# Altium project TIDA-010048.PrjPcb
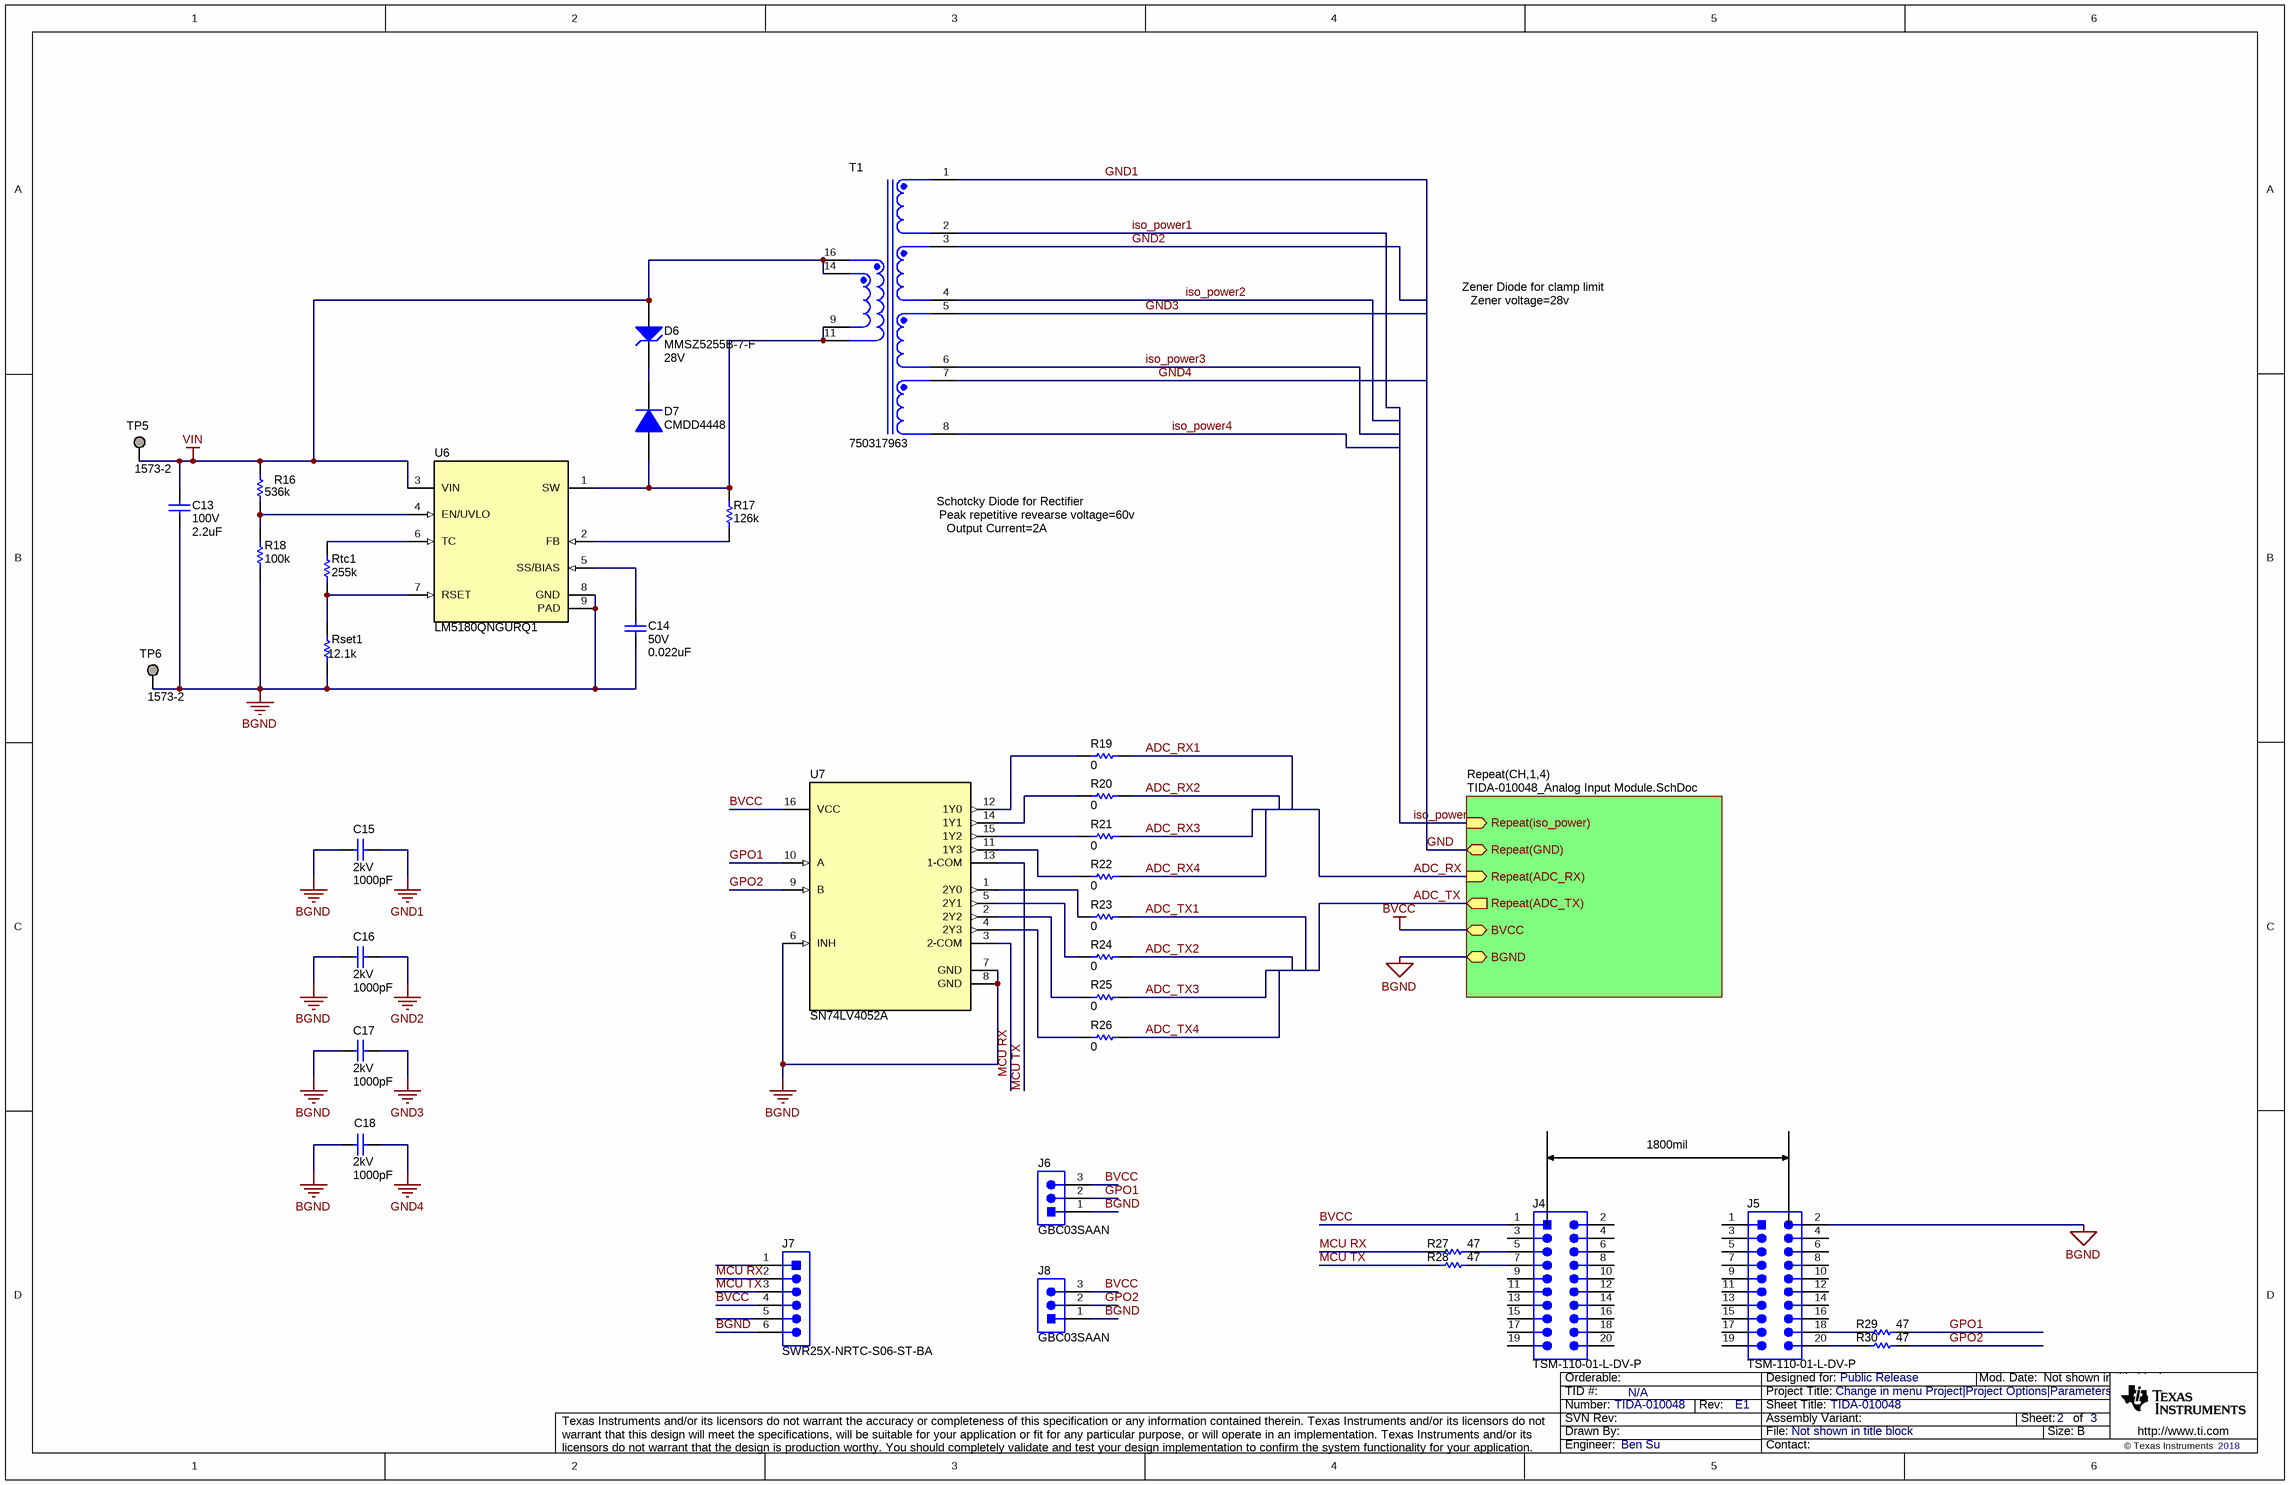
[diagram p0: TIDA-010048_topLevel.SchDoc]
Contact: http://www.ti.com/support; CopyrightYear: 2018; PCB_Layout: Who did the Layout?; PCB_Rev: E1; PRJ_Customer: Public Release; PRJ_Engineer: Ben Su; PRJ_Number: TIDA-010048; PRJ_Title: Change in menu Project|Project Options|Parameters; SCH_Rev: E1; TID: N/A
4 sheets, 256 parts. Net scope: hierarchical (ports join the sheet entries above them; power ports are global).
Board file: TIDA-010048_PCB.PcbDoc
Sheets:
  TIDA-010048_topLevel.SchDoc
    CH1 = TIDA-010048_Analog Input Module.SchDoc
    CH2 = TIDA-010048_Analog Input Module.SchDoc
    CH3 = TIDA-010048_Analog Input Module.SchDoc
    CH4 = TIDA-010048_Analog Input Module.SchDoc
  TIDA-010048_CoverSheet.SchDoc
  TIDA-010048_EVM_Hardware.SchDoc

## Sheet TIDA-010048_topLevel.SchDoc: TIDA-010048
size 431 x 279 mm; Date: Not shown in title block; ApprovedBy: Not shown in title block; CheckedBy: Not shown in title block; Author: Not shown in title block; CompanyName: Not shown in title block; Engineer: Not shown in title block; Organization: Not shown in title block; Address1: Not shown in title block; Address2: Not shown in title block; Address3: Not shown in title block; Address4: Not shown in title block; DocumentNumber: 1; Revision: Use project parameter SCH_Rev; SheetNumber: 2; SheetTotal: 3; PageSetup: Record=PageOptions¦CenterHorizontal=True¦CenterVertical=True¦PrintScale=1.00¦XCorrection=1.00¦YCorrection=1.00¦PrintKind=0¦BorderSize=5000000¦LeftOffset=0¦BottomOffset=0¦Orientation=2¦PaperLength=1000¦PaperWidth=1000¦Scale=100¦PaperSource=15¦PrintQuality=600¦MediaType=1¦DitherType=10¦PaperKind=Letter¦PrintScaleMode=1

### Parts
C13  VDC_V: 100V  ValueDisplayed: 2.2uF  [1210_210]  (hidden comment: C1210C225K1RACTU)
C14  VDC_V: 50V  ValueDisplayed: 0.022uF  [0603]  (hidden comment: C0603X223K5RACTU)
C15  VDC_V: 2kV  ValueDisplayed: 1000pF  [1812]  (hidden comment: GR443QR73D102KW01L)
C16  VDC_V: 2kV  ValueDisplayed: 1000pF  [1812]  (hidden comment: GR443QR73D102KW01L)
C17  VDC_V: 2kV  ValueDisplayed: 1000pF  [1812]  (hidden comment: GR443QR73D102KW01L)
C18  VDC_V: 2kV  ValueDisplayed: 1000pF  [1812]  (hidden comment: GR443QR73D102KW01L)
D6  MMSZ5255B-7-F  value 28V  [SOD-123]
D7  CMDD4448  [SOD-323]
J4  TSM-110-01-L-DV-P  [CONN_TSM-110-01-T-DV-P]
J5  TSM-110-01-L-DV-P  [CONN_TSM-110-01-T-DV-P]
J6  GBC03SAAN  [Sullins_Gxx03SAAN]
J7  SWR25X-NRTC-S06-ST-BA  [Sullins_SWR25X-NRTC-S06-ST-BA]
J8  GBC03SAAN  [Sullins_Gxx03SAAN]
R16  ValueDisplayed: 536k  [0603]  (hidden comment: RC0603FR-07536KL)
R17  ValueDisplayed: 126k  [0603]  (hidden comment: RT0603DRE07126KL)
R18  ValueDisplayed: 100k  [0603]  (hidden comment: RC0603FR-07100KL)
R19  ValueDisplayed: 0  [0603]  (hidden comment: CRCW06030000Z0EA)
R20  ValueDisplayed: 0  [0603]  (hidden comment: CRCW06030000Z0EA)
R21  ValueDisplayed: 0  [0603]  (hidden comment: CRCW06030000Z0EA)
R22  ValueDisplayed: 0  [0603]  (hidden comment: CRCW06030000Z0EA)
R23  ValueDisplayed: 0  [0603]  (hidden comment: CRCW06030000Z0EA)
R24  ValueDisplayed: 0  [0603]  (hidden comment: CRCW06030000Z0EA)
R25  ValueDisplayed: 0  [0603]  (hidden comment: CRCW06030000Z0EA)
R26  ValueDisplayed: 0  [0603]  (hidden comment: CRCW06030000Z0EA)
R27  ValueDisplayed: 47  [0603]  (hidden comment: CRCW060347R0JNEA)
R28  ValueDisplayed: 47  [0603]  (hidden comment: CRCW060347R0JNEA)
R29  ValueDisplayed: 47  [0603]  (hidden comment: CRCW060347R0JNEA)
R30  ValueDisplayed: 47  [0603]  (hidden comment: CRCW060347R0JNEA)
Rset1  ValueDisplayed: 12.1k  [0603]  (hidden comment: RC0603FR-0712K1L)
Rtc1  ValueDisplayed: 255k  [0603]  (hidden comment: RC0603FR-07255KL)
T1  750317963  [Wurth_750317963]
TP5  1573-2  [Keystone1573-2]
TP6  1573-2  [Keystone1573-2]
U6  LM5180QNGURQ1  [NGU0008C]
U7  SN74LV4052A  [PW0016A_L]

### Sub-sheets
Repeat(CH,1,4) = TIDA-010048_Analog Input Module.SchDoc: Repeat(iso_power) (in), Repeat(ADC_TX) (out), Repeat(ADC_RX) (in), BVCC (bidir), Repeat(GND), BGND (bidir)

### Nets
BGND: C13.2 C14.2 C15.2 C16.2 C17.2 C18.2 J5.2 J6.1 J7.6 J8.1 R18.1 Rset1.1 TP6.1 U6.8(GND) U6.9(PAD) U7.6(INH) U7.7(GND) U7.8(GND) ; sheet Repeat(CH,1,4)/BGND
BVCC: J4.1 J6.3 J7.4 J8.3 U7.16(VCC) ; sheet Repeat(CH,1,4)/BVCC
GND1: C15.1 C16.1 C17.1 C18.1 T1.1 T1.3 T1.5 T1.7  [also labelled GND2, GND3, GND4]  [project net GND]
VIN: C13.1 D6.2(A) R16.2 T1.14 T1.16 TP5.1 U6.3(VIN)
ADC_RX1: R19.2
ADC_RX2: R20.2
ADC_RX3: R21.2
ADC_RX4: R22.2
ADC_TX1: R23.2
ADC_TX2: R24.2
ADC_TX3: R25.2
ADC_TX4: R26.2
GPO1: J6.2 R29.2 U7.10(A)
GPO2: J8.2 R30.2 U7.9(B)
iso_power1: T1.2
iso_power2: T1.4
iso_power3: T1.6
iso_power4: T1.8
MCU RX: J7.2 R27.1 U7.3(2-COM)
MCU TX: J7.3 R28.1 U7.13(1-COM)
NetC14_1: C14.1 U6.5(SS/BIAS)
NetD6_1: D6.1(K) D7.1(K)
NetD7_2: D7.2(A) R17.2 T1.9 T1.11 U6.1(SW)
NetJ4_5: J4.5 R27.2
NetJ4_7: J4.7 R28.2
NetJ5_18: J5.18 R29.1
NetJ5_20: J5.20 R30.1
NetR16_1: R16.1 R18.2 U6.4(EN/UVLO)
NetR17_1: R17.1 U6.2(FB)
NetR19_1: R19.1 U7.12(1Y0)
NetR20_1: R20.1 U7.14(1Y1)
NetR21_1: R21.1 U7.15(1Y2)
NetR22_1: R22.1 U7.11(1Y3)
NetR23_1: R23.1 U7.1(2Y0)
NetR24_1: R24.1 U7.5(2Y1)
NetR25_1: R25.1 U7.2(2Y2)
NetR26_1: R26.1 U7.4(2Y3)
NetRset1_2: Rset1.2 Rtc1.1 U6.7(RSET)
NetRtc1_2: Rtc1.2 U6.6(TC)

Not connected (* = marked no-connect by the designer): J4 2 3 4 6 8 9 10 11 12 13 14 15 16 17 18 19 20; J5 1 3 4 5 6 7 8 9 10 11 12 13 14 15 16 17 19; J7 1 5

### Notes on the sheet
- Zener voltage=28v
- Zener Diode for clamp limit
- Schotcky Diode for Rectifier
- Output Current=2A
- Peak repetitive revearse voltage=60v
- 1800mil

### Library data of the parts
C13 = CMP-0009084-1: CAP, CERM, 2.2 uF, 100 V, +/- 10%, X7R, 1210; Manufacturer: Kemet; TaMin_C: -55°C; Polarized: N; SizeAreaWB_mm2: 14.7; Value1: Unknown; U/M: EA; Value: 2.2uF; TaMax_C: 125°C; SizeZ_mm: 2.1; SizeX_mm: 3.2; SizeY_mm: 2.5; Cap_Case: 1210; SizeArea_mm2: 8; CompType: Capacitor; Cap_F: 2.2µF; AEC Category: Q200
C14 = CMP-0006984-4: CAP, CERM, 0.022 uF, 50 V, +/- 10%, X7R, 0603; Manufacturer: Kemet; TaMin_C: -55°C; Polarized: N; SizeAreaWB_mm2: 4.68; Value1: Unknown; U/M: EA; TaMax_C: 125°C; SizeZ_mm: 1; SizeX_mm: 1.6; SizeY_mm: 0.8; SizeArea_mm2: 1.28; CompType: Capacitor; Cap_F: 22nF; AEC Category: Q200
C15-C18 = CMP-0009438-2: CAP, CERM, 1000 pF, 2000 V, +/- 10%, X7R, 1812; Manufacturer: MuRata; TaMin_C: -55°C; Polarized: N; SizeAreaWB_mm2: 23.1; Value1: Unknown; U/M: EA; Value: 1000pF; TaMax_C: 125°C; SizeZ_mm: 1.35; SizeX_mm: 4.5; SizeY_mm: 3.2; Value2: 2000V; SizeArea_mm2: 14.4; Cap_F: 1nF; AEC Category: Q200
D6 = CMP-0005760-4: Diode, Zener, 28 V, 500 mW, SOD-123; Manufacturer: Diodes Inc.; SizeArea_mm2: 6.545; Value1: 0.5W; SizeZ_mm: 1.35; AEC Category: Q101; SizeY_mm: 1.7; Power_W: 500mW; SizeAreaWB_mm2: 13.095; RJA_CperW: 350; SizeX_mm: 3.85
D7 = CMP-0029019-2: Diode, Ultrafast, 75 V, 0.25 A, SOD-323; Manufacturer: Central Semiconductor; Io_A: 2.5dA; SizeX_mm: 2.7; Vf_V: 1.2V; TJmax_C: 175°C; SizeAreaWB_mm2: 8.695; SizeArea_mm2: 3.645; Vr_V: 75V; Green_Lifecycle: Not Set; Green_REACh: Incomplete; AEC Category: Q101; Value: 75V; Value1: 0.25A; SizeZ_mm: 1; SizeY_mm: 1.35
J4 J5 = CMP-0075600-1: Header, 2.54mm, 10x2, Gold, SMT; Manufacturer: Samtec; Pitch_mm: 2.54; Gender: Male; Cert_CSA: Y; Green_REACh: Passed; Current_A: 5.4A; Voltage_V: 475V; CT: False; Shrouded: N; Green_Lifecycle: Active; Row_Count: 2; CNHeader: True
J6 J8 = CMP-0054577-1: Header, 2.54 mm, 3x1, Gold, TH; Manufacturer: Sullins Connector Solutions; CT: FALSE; CNHeader: TRUE
J7 = CMP-0054740-1: Header, 2.54mm, 6x1, Tin, TH; Manufacturer: Sullins Connector Solutions; CNHeader: FALSE; Current_A: 3A; Gender: Male; Voltage_V: 250V; Row_Count: 1; Pitch_mm: 2.54; Cert_UL: Y
R16 = CMP-0023174-4: RES, 536 k, 1%, 0.1 W, 0603; Manufacturer: Yageo; Power_W: 100mW; TempCo: 100 ppm/C; Value: 536k; EIA_Code: E96; SizeX_mm: 1.6; SizeY_mm: 0.8; SizeZ_mm: 1; Value2: 0.1W; SizeArea_mm2: 1.28; CompType: Resistor; AEC Qualified: N; VDC_V: 75V; AEC Category: Q200; SizeAreaWB_mm2: 4.68
R17 = CMP-0024631-2: RES, 126 k, 0.5%, 0.1 W, 0603; Manufacturer: Yageo America; Power_W: 100mW; TempCo: 50 ppm/C; U/M: EA; Value: 126k; EIA_Code: E192; SizeX_mm: 1.6; SizeY_mm: 0.8; SizeZ_mm: 1; Value2: 0.1W; SizeArea_mm2: 1.28; CompType: Resistor; VDC_V: 75V; AEC Category: Q200
R18 = CMP-0022735-5: RES, 100 k, 1%, 0.1 W, 0603; Manufacturer: Yageo; Power_W: 100mW; TempCo: 100 ppm/C; Value: 100k; EIA_Code: E96; SizeX_mm: 1.6; SizeY_mm: 0.8; SizeZ_mm: 1; Value2: 0.1W; SizeArea_mm2: 1.28; CompType: Resistor; AEC Qualified: N; VDC_V: 75V; AEC Category: Q200; SizeAreaWB_mm2: 4.68
R19-R26 = CMP-0025697-4: RES, 0, 5%, 0.1 W, AEC-Q200 Grade 0, 0603; Manufacturer: Vishay-Dale; Power_W: 100mW; TempCo: 200 ppm/C; Value_Code: 0000; Value: 0; EIA_Code: E24; SizeX_mm: 1.6; SizeY_mm: 0.8; SizeZ_mm: 1; Value2: 0.1W; SizeArea_mm2: 1.28; AEC Qualified: Y; VDC_V: 75V; AEC Category: Q200
R27-R30 = CMP-0025815-2: RES, 47, 5%, 0.1 W, 0603; Manufacturer: Vishay-Dale; Power_W: 100mW; TempCo: 200 ppm/C; Value_Code: 47R0; U/M: EA; Value: 47; EIA_Code: E24; SizeX_mm: 1.6; SizeY_mm: 0.8; SizeZ_mm: 1; Value2: 0.1W; SizeArea_mm2: 1.28; VDC_V: 75V; AEC Category: Q200
Rset1 = CMP-0022776-5: RES, 12.1 k, 1%, 0.1 W, 0603; Manufacturer: Yageo; Power_W: 100mW; TempCo: 100 ppm/C; Value_Code: 12k1; Value: 12.1k; EIA_Code: E96; SizeX_mm: 1.6; SizeY_mm: 0.8; SizeZ_mm: 1; Value2: 0.1W; SizeArea_mm2: 1.28; CompType: Resistor; AEC Qualified: N; VDC_V: 75V; AEC Category: Q200; SizeAreaWB_mm2: 4.68
Rtc1 = CMP-0022949-4: RES, 255 k, 1%, 0.1 W, 0603; Manufacturer: Yageo; Power_W: 100mW; TempCo: 100 ppm/C; Value: 255k; EIA_Code: E96; SizeX_mm: 1.6; SizeY_mm: 0.8; SizeZ_mm: 1; Value2: 0.1W; SizeArea_mm2: 1.28; CompType: Resistor; AEC Qualified: N; VDC_V: 75V; AEC Category: Q200; SizeAreaWB_mm2: 4.68
T1 = CMP-0084723-1: Transformer, 22 uH, TH; Manufacturer: Wurth Elektronik; Rsec2_ohm: 4.25d; DCR_ohm: 0.036; Value: 22uH; Ind_H: 22µH; LeakageInd_H: 75nH; SizeArea_mm2: 213.0425; SizeAreaWB_mm2: 275.4825; SizeY_mm: 15.25; Ns1toNp: 2; SizeX_mm: 13.97; Rsec3_ohm: 5.15d; AEC Qualified: N; AEC Category: Q200; Lp: 22; SizeZ_mm: 12.7
TP5 TP6 = CMP-0055119-1: Terminal, Turret, TH, Double; Manufacturer: Keystone; CT: FALSE; Green_REACh: Passed; CompType: Turret Terminal; Green_Lifecycle: Active
U6 = CMP-0078633-2: 70-V PSR Flyback Converter With 100-V, 1.2-A Power Switch and Ultra-Low IQ, NGU0008C (WSON-8); Alternate PartNumber: LM5180QNGUTQ1; Alternate Manufacturer: Texas Instruments; SizeAreaWB_mm2: 25; SizeZ_mm: 0.8; SizeX_mm: 4; SizeArea_mm2: 16; CompType: IC; AEC Qualified: Y; AEC Category: Q200
U7 = CMP-0066257-1: Automotive Catalog Dual 4-Channel Analog Multiplexer/Demultiplexer, PW0016A (TSSOP-16); Alternate Manufacturer: Texas Instruments; SizeAreaWB_mm2: 58.8; U/M: EA; SizeZ_mm: 1.2; SizeX_mm: 6.4; SizeY_mm: 5.0; SizeArea_mm2: 32.0; CompType: IC

## Sheet TIDA-010048_Analog Input Module.SchDoc
size 431 x 279 mm; Date: Not shown in title block; ApprovedBy: Not shown in title block; CheckedBy: Not shown in title block; Author: Not shown in title block; CompanyName: Not shown in title block; Engineer: Not shown in title block; Organization: Not shown in title block; Address1: Not shown in title block; Address2: Not shown in title block; Address3: Not shown in title block; Address4: Not shown in title block; DocumentNumber: 1; Revision: Use project parameter SCH_Rev; SheetNumber: 2; SheetTotal: 3; PageSetup: Record=PageOptions¦CenterHorizontal=True¦CenterVertical=True¦PrintScale=1.00¦XCorrection=1.00¦YCorrection=1.00¦PrintKind=0¦BorderSize=5000000¦LeftOffset=0¦BottomOffset=0¦Orientation=2¦PaperLength=1000¦PaperWidth=1000¦Scale=100¦PaperSource=15¦PrintQuality=600¦MediaType=1¦DitherType=10¦PaperKind=Letter¦PrintScaleMode=1
Used 4 times, as channels CH1, CH2, CH3, CH4. Parts and nets are listed once, with the designators drawn on the sheet.
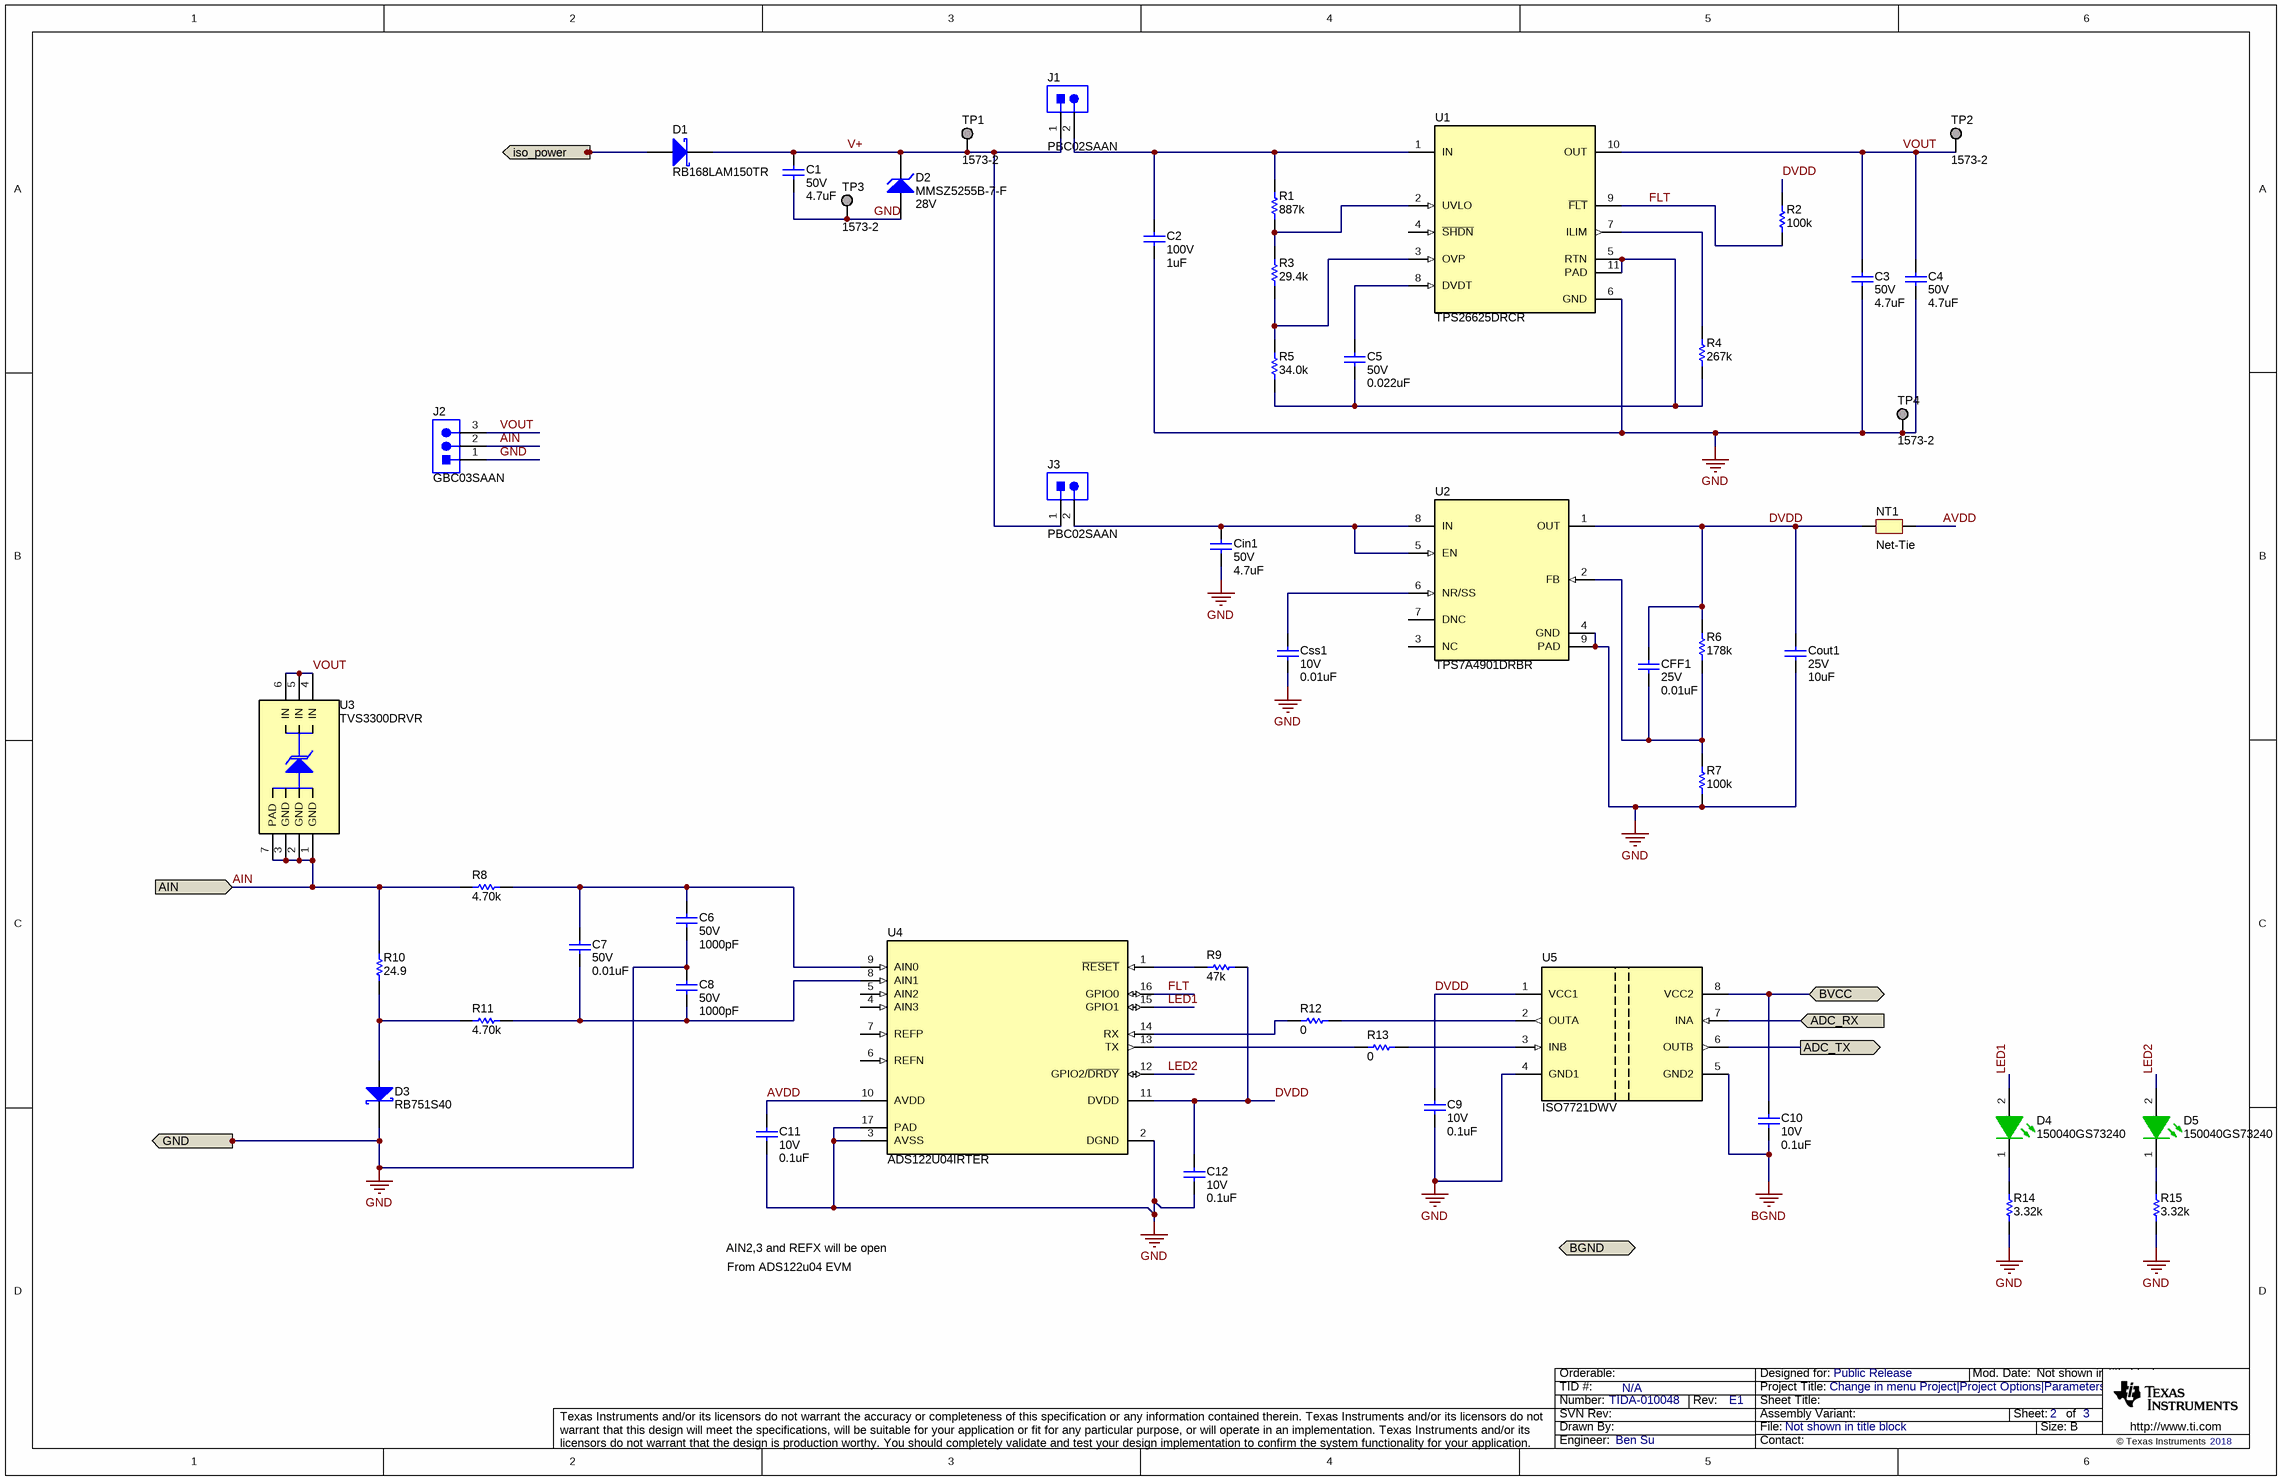
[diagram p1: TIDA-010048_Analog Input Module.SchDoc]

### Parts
C1  VDC_V: 50V  ValueDisplayed: 4.7uF  [0805_HV]  (hidden comment: C2012X5R1H475K125AB)
C2  VDC_V: 100V  ValueDisplayed: 1uF  [1206_180]  (hidden comment: C3216X7R2A105K160AA)
C3  VDC_V: 50V  ValueDisplayed: 4.7uF  [0805_HV]  (hidden comment: C2012X5R1H475K125AB)
C4  VDC_V: 50V  ValueDisplayed: 4.7uF  [0805_HV]  (hidden comment: C2012X5R1H475K125AB)
C5  VDC_V: 50V  ValueDisplayed: 0.022uF  [0603]  (hidden comment: C0603X223K5RACTU)
C6  VDC_V: 50V  ValueDisplayed: 1000pF  [0603]  (hidden comment: C0603C102J5GACTU)
C7  VDC_V: 50V  ValueDisplayed: 0.01uF  [0603]  (hidden comment: GRM1885C1H103JA01D)
C8  VDC_V: 50V  ValueDisplayed: 1000pF  [0603]  (hidden comment: C0603C102J5GACTU)
C9  VDC_V: 10V  ValueDisplayed: 0.1uF  [0603]  (hidden comment: C0603C104K8RACTU)
C10  VDC_V: 10V  ValueDisplayed: 0.1uF  [0603]  (hidden comment: C0603C104K8RACTU)
C11  VDC_V: 10V  ValueDisplayed: 0.1uF  [0603]  (hidden comment: C0603C104K8RACTU)
C12  VDC_V: 10V  ValueDisplayed: 0.1uF  [0603]  (hidden comment: C0603C104K8RACTU)
CFF1  VDC_V: 25V  ValueDisplayed: 0.01uF  [0603]  (hidden comment: GRM188R71E103KA01D)
Cin1  VDC_V: 50V  ValueDisplayed: 4.7uF  [0805_HV]  (hidden comment: C2012X5R1H475K125AB)
Cout1  VDC_V: 25V  ValueDisplayed: 10uF  [1210_280]  (hidden comment: C3225X7R1E106M250AC)
Css1  VDC_V: 10V  ValueDisplayed: 0.01uF  [0603]  (hidden comment: 0603ZC103KAT2A)
D1  RB168LAM150TR  [SOD-128]
D2  MMSZ5255B-7-F  value 28V  [SOD-123]
D3  RB751S40  [Fairchild_SOD-523F]
D4  150040GS73240  [WL-SMCC_0402_Green]
D5  150040GS73240  [WL-SMCC_0402_Green]
J1  PBC02SAAN  [Sullins_PBC02SAAN]
J2  GBC03SAAN  [Sullins_Gxx03SAAN]
J3  PBC02SAAN  [Sullins_PBC02SAAN]
NT1  Net-Tie  [Net-Tie_0805_HV_NoOverlay]  (net tie, no BOM)
R1  ValueDisplayed: 887k  [0603]  (hidden comment: RC0603FR-07887KL)
R2  ValueDisplayed: 100k  [0603]  (hidden comment: RC0603FR-07100KL)
R3  ValueDisplayed: 29.4k  [0603]  (hidden comment: RC0603FR-0729K4L)
R4  ValueDisplayed: 267k  [0603]  (hidden comment: RC0603FR-07267KL)
R5  ValueDisplayed: 34.0k  [0603]  (hidden comment: RC0603FR-0734KL)
R6  ValueDisplayed: 178k  [0603]  (hidden comment: CRCW0603178KFKEA)
R7  ValueDisplayed: 100k  [0603]  (hidden comment: RC0603FR-07100KL)
R8  ValueDisplayed: 4.70k  [0805_HV]  (hidden comment: ERJ-P06F4701V)
R9  ValueDisplayed: 47k  [0603]  (hidden comment: CRCW060347K0JNEA)
R10  ValueDisplayed: 24.9  [0603]  (hidden comment: RNCF0603TKY24R9)
R11  ValueDisplayed: 4.70k  [0805_HV]  (hidden comment: ERJ-P06F4701V)
R12  ValueDisplayed: 0  [0603]  (hidden comment: CRCW06030000Z0EA)
R13  ValueDisplayed: 0  [0603]  (hidden comment: CRCW06030000Z0EA)
R14  ValueDisplayed: 3.32k  [0603]  (hidden comment: RC0603FR-073K32L)
R15  ValueDisplayed: 3.32k  [0603]  (hidden comment: RC0603FR-073K32L)
TP1  1573-2  [Keystone1573-2]
TP2  1573-2  [Keystone1573-2]
TP3  1573-2  [Keystone1573-2]
TP4  1573-2  [Keystone1573-2]
U1  TPS26625DRCR  [DRC0010J]
U2  TPS7A4901DRBR  [DRB0008A]
U3  TVS3300DRVR  [DRV0006A]
U4  ADS122U04IRTER  [RTE0016D]
U5  ISO7721DWV  [DWV0008A]

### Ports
ADC_RX (in), ADC_TX (out), AIN (in), BGND (bidir), BVCC (bidir), GND, iso_power (in)

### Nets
BGND: C10.2 U5.5(GND2)
GND: C1.2 C2.2 C3.2 C4.2 C6.2 C8.1 C9.2 C11.2 C12.2 Cin1.2 Cout1.2 Css1.2 D2.2(A) D3.1(K) J2.1 R7.1 R14.1 R15.1 TP3.1 TP4.1 U1.6(GND) U2.4(GND) U2.9(PAD) U4.2(DGND) U4.3(AVSS) U4.17(PAD) U5.4(GND1) ; port GND
ADC_RX: U5.7(INA) ; port ADC_RX
ADC_TX: U5.6(OUTB) ; port ADC_TX
AIN: J2.2 R8.1 R10.2 U3.1(GND) U3.2(GND) U3.3(GND) U3.7(PAD) ; port AIN
AVDD: C11.1 NT1.2 U4.10(AVDD)
BVCC: C10.1 U5.8(VCC2) ; port BVCC
DVDD: C9.1 C12.1 CFF1.1 Cout1.1 NT1.1 R2.2 R6.2 R9.2 U2.1(OUT) U4.11(DVDD) U5.1(VCC1)
FLT: R2.1 U1.9(~{FLT}) U4.16(GPIO0)
iso_power: D1.2(A) ; port iso_power
LED1: D4.2(A) U4.15(GPIO1)
LED2: D5.2(A) U4.12(GPIO2/~{DRDY})
V+: C1.1 D1.1(K) D2.1(K) J1.1 J3.1 TP1.1
VOUT: C3.1 C4.1 J2.3 TP2.1 U1.10(OUT) U3.4(IN) U3.5(IN) U3.6(IN)
NetC2_1: C2.1 J1.2 R1.2 U1.1(IN)
NetC5_1: C5.1 U1.8(DVDT)
NetC5_2: C5.2 R4.1 R5.1 U1.5(RTN) U1.11(PAD)
NetC6_1: C6.1 C7.1 R8.2 U4.9(AIN0)
NetC7_2: C7.2 C8.2 R11.2 U4.8(AIN1)
NetCFF1_2: CFF1.2 R6.1 R7.2 U2.2(FB)
NetCin1_1: Cin1.1 J3.2 U2.5(EN) U2.8(IN)
NetCss1_1: Css1.1 U2.6(NR/SS)
NetD3_2: D3.2(A) R10.1 R11.1
NetD4_1: D4.1(K) R14.2
NetD5_1: D5.1(K) R15.2
NetR1_1: R1.1 R3.2 U1.2(UVLO)
NetR3_1: R3.1 R5.2 U1.3(OVP)
NetR4_2: R4.2 U1.7(ILIM)
NetR9_1: R9.1 U4.1(~{RESET})
NetR12_1: R12.1 U4.14(RX)
NetR12_2: R12.2 U5.2(OUTA)
NetR13_1: R13.1 U4.13(TX)
NetR13_2: R13.2 U5.3(INB)

Not connected (* = marked no-connect by the designer): U1 4(~{SHDN}); U2 3(NC) 7(DNC); U4 4(AIN3) 5(AIN2) 6(REFN) 7(REFP)

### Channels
CH1: designators end in _CH1; ports ADC_RX=ADC_RX1 ADC_TX=ADC_TX1 AIN=AIN_CH1 BGND=BGND BVCC=BVCC GND=GND iso_power=iso_power1
CH2: designators end in _CH2; ports ADC_RX=ADC_RX2 ADC_TX=ADC_TX2 AIN=AIN_CH2 BGND=BGND BVCC=BVCC GND=GND iso_power=iso_power2
CH3: designators end in _CH3; ports ADC_RX=ADC_RX3 ADC_TX=ADC_TX3 AIN=AIN_CH3 BGND=BGND BVCC=BVCC GND=GND iso_power=iso_power3
CH4: designators end in _CH4; ports ADC_RX=ADC_RX4 ADC_TX=ADC_TX4 AIN=AIN_CH4 BGND=BGND BVCC=BVCC GND=GND iso_power=iso_power4

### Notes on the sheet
- From ADS122u04 EVM
- AIN2,3 and REFX will be open

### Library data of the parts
C1 C3 C4 Cin1 = CMP-0007840-2: CAP, CERM, 4.7 uF, 50 V, +/- 10%, X5R, 0805; Manufacturer: TDK; TaMin_C: -55°C; ESR_ohm: 2.346m; Polarized: N; SizeAreaWB_mm2: 6.75; Value1: 0.002346 ohm; U/M: EA; Value: 4.7uF; TaMax_C: 85°C; SizeZ_mm: 1.45; SizeX_mm: 2; SizeY_mm: 1.25; Cap_Case: 0805; SizeArea_mm2: 2.5; CompType: Capacitor; Cap_F: 4.7µF; IRMS_A: 4.26021A; AEC Category: Q200
C2 = CMP-0008710-2: CAP, CERM, 1 uF, 100 V, +/- 10%, X7R, 1206; Manufacturer: TDK; TaMin_C: -55°C; ESR_ohm: 4.575m; Polarized: N; SizeAreaWB_mm2: 10.92; Value1: 0.004575 ohm; U/M: EA; Value: 1uF; TaMax_C: 125°C; SizeZ_mm: 1.8; SizeX_mm: 3.2; SizeY_mm: 1.6; SizeArea_mm2: 5.12; CompType: Capacitor; Cap_F: 1µF; IRMS_A: 3.39639A; AEC Category: Q200
C5 = CMP-0006984-4: as C14 on sheet TIDA-010048_topLevel
C6 C8 = CMP-0006843-4: CAP, CERM, 1000 pF, 50 V, +/- 5%, C0G/NP0, 0603; Manufacturer: Kemet; TaMin_C: -55°C; Polarized: N; SizeAreaWB_mm2: 4.68; Value1: Unknown; U/M: EA; Value: 1000pF; TaMax_C: 125°C; SizeZ_mm: 1; SizeX_mm: 1.6; SizeY_mm: 0.8; SizeArea_mm2: 1.28; CompType: Capacitor; Cap_F: 1nF; AEC Category: Q200
C7 = CMP-0007174-4: CAP, CERM, 0.01 uF, 50 V, +/- 5%, C0G/NP0, 0603; Manufacturer: MuRata; TaMin_C: -55°C; Polarized: N; SizeAreaWB_mm2: 4.68; Value1: Unknown; U/M: EA; Value: 0.01uF; TaMax_C: 125°C; SizeZ_mm: 1; SizeX_mm: 1.6; SizeY_mm: 0.8; SizeArea_mm2: 1.28; CompType: Capacitor; Cap_F: 10nF; AEC Category: Q200
C9-C12 = CMP-0006862-5: CAP, CERM, 0.1 uF, 10 V, +/- 10%, X7R, 0603; Manufacturer: Kemet; TaMin_C: -55°C; Polarized: N; SizeAreaWB_mm2: 4.68; Value1: Unknown; U/M: EA; Value: 0.1uF; TaMax_C: 125°C; SizeZ_mm: 1; SizeX_mm: 1.6; SizeY_mm: 0.8; SizeArea_mm2: 1.28; CompType: Capacitor; Cap_F: 100nF; AEC Category: Q200
CFF1 = CMP-0007403-4: CAP, CERM, 0.01 uF, 25 V, +/- 10%, X7R, 0603; Manufacturer: MuRata; TaMin_C: -55°C; Polarized: N; SizeAreaWB_mm2: 4.68; Value1: Unknown; U/M: EA; Value: 0.01uF; TaMax_C: 125°C; SizeZ_mm: 1; SizeX_mm: 1.6; SizeY_mm: 0.8; SizeArea_mm2: 1.28; CompType: Capacitor; Cap_F: 10nF; AEC Category: Q200
Cout1 = CMP-0009117-1: CAP, CERM, 10 uF, 25 V, +/- 20%, X7R, 1210; Manufacturer: TDK; TaMin_C: -55°C; Polarized: N; SizeAreaWB_mm2: 14.7; Value1: Unknown; U/M: EA; Value: 10uF; TaMax_C: 125°C; SizeZ_mm: 2.8; SizeX_mm: 3.2; SizeY_mm: 2.5; Cap_Case: 1210; SizeArea_mm2: 8; CompType: Capacitor; Cap_F: 10µF; AEC Category: Q200
Css1 = CMP-0006814-5: CAP, CERM, 0.01 uF, 10 V, +/- 10%, X7R, 0603; Manufacturer: AVX; TaMin_C: -55°C; Polarized: N; SizeAreaWB_mm2: 4.68; Value1: Unknown; U/M: EA; Value: 0.01uF; TaMax_C: 125°C; SizeZ_mm: 1; SizeX_mm: 1.6; SizeY_mm: 0.8; SizeArea_mm2: 1.28; CompType: Capacitor; Cap_F: 10nF; AEC Category: Q200
D1 = CMP-0080711-2: Diode, Schottky, 150 V, 1 A, SOD-128; Manufacturer: Rohm; AEC Category: Q101; AEC Qualified: N; TJmax_C: 150°C; Io_A: 1A; Vr_V: 150V; Value: 150V; Vf_V: 8.4dV; SizeX_mm: 4.6; SizeAreaWB_mm2: 19.6; Value2: 0.84V; SizeY_mm: 2.5; SizeZ_mm: 1.1; SizeArea_mm2: 11.5
D2 = CMP-0005760-3: Diode, Zener, 28 V, 500 mW, SOD-123; Manufacturer: Diodes Inc.; SizeX_mm: 3.85; AEC Category: Q101; SizeAreaWB_mm2: 13.095; Value1: 0.5W; SizeZ_mm: 1.35; RJA_CperW: 350; Power_W: 500mW; SizeArea_mm2: 6.545; SizeY_mm: 1.7
D3 = CMP-0028860-2: Diode, Schottky, 40 V, 0.03 A, SOD-523F; Manufacturer: Fairchild Semiconductor; SizeX_mm: 1.6; SizeY_mm: 0.8; Value1: 0.03A; TJmax_C: 125°C; AEC Qualified: N; SizeArea_mm2: 1.28; Vf_V: 3.7dV; AEC Category: Q101; Value: 40V; Io_A: 30mA; SizeAreaWB_mm2: 4.68; Value2: 0.37V; SizeZ_mm: 0.7; Green_Lifecycle: Not Set; Green_REACh: Incomplete
D4 D5 = CMP-0081765-2: LED, Green, SMD; Manufacturer: Wurth Elektronik; Vr_V: 5V; Io_A: 20mA; Tjmax_C: 95°C; Ir_A: 10µA; Power_TotalModule: 99mW; Value2: 3.2V; SizeArea_mm2: 0.5; SizeX_mm: 1; Value1: 0.099W; Angle: 120; Type: InGaN; SizeAreaWB_mm2: 3
J1 J3 = CMP-0054566-1: Header, 100mil, 2x1, Gold, TH; Manufacturer: Sullins Connector Solutions; CNHeader: TRUE; Current_A: 3A; Green_Lifecycle: Active; Shrouded: N; Gender: Male; Green_REACh: Passed; Voltage_V: 1.8kV; Row_Count: 1; Pitch_mm: 2.54; CT: FALSE; Cert_UL: Y
J2 = CMP-0054577-1: as J6 on sheet TIDA-010048_topLevel
NT1 = CMP-0078142-2: Single point connection between nets.
R1 = CMP-0023302-4: RES, 887 k, 1%, 0.1 W, 0603; Manufacturer: Yageo; Power_W: 100mW; TempCo: 100 ppm/C; Value: 887k; EIA_Code: E96; SizeX_mm: 1.6; SizeY_mm: 0.8; SizeZ_mm: 1; Value2: 0.1W; SizeArea_mm2: 1.28; CompType: Resistor; AEC Qualified: N; VDC_V: 75V; AEC Category: Q200; SizeAreaWB_mm2: 4.68
R2 R7 = CMP-0022735-5: as R18 on sheet TIDA-010048_topLevel
R3 = CMP-0022979-5: RES, 29.4 k, 1%, 0.1 W, 0603; Manufacturer: Yageo; Power_W: 100mW; TempCo: 100 ppm/C; Value_Code: 29k4; Value: 29.4k; EIA_Code: E96; SizeX_mm: 1.6; SizeY_mm: 0.8; SizeZ_mm: 1; Value2: 0.1W; SizeArea_mm2: 1.28; CompType: Resistor; AEC Qualified: N; VDC_V: 75V; AEC Category: Q200; SizeAreaWB_mm2: 4.68
R4 = CMP-0022955-4: RES, 267 k, 1%, 0.1 W, 0603; Manufacturer: Yageo; Power_W: 100mW; TempCo: 100 ppm/C; Value: 267k; EIA_Code: E96; SizeX_mm: 1.6; SizeY_mm: 0.8; SizeZ_mm: 1; Value2: 0.1W; SizeArea_mm2: 1.28; CompType: Resistor; AEC Qualified: N; VDC_V: 75V; AEC Category: Q200; SizeAreaWB_mm2: 4.68
R5 = CMP-0023045-5: RES, 34.0 k, 1%, 0.1 W, 0603; Manufacturer: Yageo; Power_W: 100mW; TempCo: 100 ppm/C; Value_Code: 34k0; Value: 34.0k; EIA_Code: E96; Res_ohm: 34k; SizeX_mm: 1.6; SizeY_mm: 0.8; SizeZ_mm: 1; Value2: 0.1W; SizeArea_mm2: 1.28; CompType: Resistor; AEC Qualified: N; VDC_V: 75V; AEC Category: Q200; SizeAreaWB_mm2: 4.68
R6 = CMP-0022087-4: RES, 178 k, 1%, 0.1 W, AEC-Q200 Grade 0, 0603; Manufacturer: Vishay-Dale; Power_W: 100mW; TempCo: 100 ppm/C; Value: 178k; EIA_Code: E96; SizeX_mm: 1.6; SizeY_mm: 0.8; SizeZ_mm: 1; Value2: 0.1W; SizeArea_mm2: 1.28; CompType: Resistor; AEC Qualified: Y; VDC_V: 75V; AEC Category: Q200; AEC Grade: 0
R8 R11 = CMP-0021852-2: RES, 4.70 k, 1%, 0.5 W, AEC-Q200 Grade 0, 0805; Manufacturer: Panasonic; Power_W: 500mW; TempCo: 100 ppm/C; Value_Code: 4k70; U/M: EA; Value: 4.70k; Res_ohm: 4.7k; SizeX_mm: 2; SizeY_mm: 1.25; SizeZ_mm: 1.45; Value2: 0.5W; SizeArea_mm2: 2.5; AEC Qualified: Y; VDC_V: 400V; AEC Grade: 0; AEC Category: Q200
R9 = CMP-0025814-2: RES, 47 k, 5%, 0.1 W, 0603; Manufacturer: Vishay-Dale; Power_W: 100mW; TempCo: 200 ppm/C; Value_Code: 47k0; U/M: EA; Value: 47k; EIA_Code: E24; SizeX_mm: 1.6; SizeY_mm: 0.8; SizeZ_mm: 1; Value2: 0.1W; SizeArea_mm2: 1.28; VDC_V: 75V; AEC Category: Q200
R10 = CMP-0083850-1: RES, 24.9, 0.01%, 0.1 W, AEC-Q200 Grade 0, 0603; Manufacturer: Stackpole Electronics Inc; Power_W: 100mW; TempCo: 5 ppm/C; SizeAreaWB_mm2: 4.68; Value_Code: 24R9; Value: 24.9; SizeX_mm: 1.6; SizeY_mm: 0.8; SizeZ_mm: 1; Value2: 0.1W; SizeArea_mm2: 1.28; CompType: Resistor; AEC Qualified: Y; VDC_V: 75V; AEC Grade: 0; AEC Category: Q200
R12 R13 = CMP-0025697-4: as R19 on sheet TIDA-010048_topLevel
R14 R15 = CMP-0023080-5: RES, 3.32 k, 1%, 0.1 W, 0603; Manufacturer: Yageo; Power_W: 100mW; TempCo: 100 ppm/C; Value_Code: 3k32; Value: 3.32k; EIA_Code: E96; SizeX_mm: 1.6; SizeY_mm: 0.8; SizeZ_mm: 1; Value2: 0.1W; SizeArea_mm2: 1.28; CompType: Resistor; AEC Qualified: N; VDC_V: 75V; AEC Category: Q200; SizeAreaWB_mm2: 4.68
TP1-TP4 = CMP-0055119-1: as TP5 on sheet TIDA-010048_topLevel
U1 = CMP-0013395-6: 60-V, 800-mA Industrial eFuse with Integrated Reverse Polarity Protection, DRC0010J (VSON-10); Alternate PartNumber: TPS26625DRCT; Manufacturer: Texas Instruments; SizeZ_mm: 1; SizeX_mm: 3; SizeArea_mm2: 9; CompType: IC; SizeAreaWB_mm2: 16; AEC Category: Q200; AEC Qualified: N; Rating: Catalog
U2 = CMP-0073868-3: Vin 3V to 36V, 150mA, Ultra-Low-Noise, High-PSRR Low-Dropout (LDO) Linear Regulator, DRB0008A (VSON-8); Manufacturer: Texas Instruments; Alternate PartNumber: TPS7A4901DRBT; AEC Category: Q200; CompType: IC; SizeZ_mm: 1.0; Rating: Catalog; SizeAreaWB_mm2: 16.0; SizeX_mm: 3.0; SizeArea_mm2: 9.0; AEC Qualified: N
U3 = CMP-0013424-7: 33-V Precision Surge Protection Clamp, DRV0006A (WSON-6); Manufacturer: Texas Instruments; Alternate PartNumber: TVS3300DRVT; SizeX_mm: 2; CompType: IC; SizeZ_mm: 0.8; SizeArea_mm2: 4; SizeAreaWB_mm2: 9; U/M: EA
U4 = CMP-0074857-3: 24-Bit, 2kSPS, 4-Ch, Low-Power Delta-Sigma ADC w/ PGA, Voltage Reference, 2x IDACs & UART Interface, RTE0016D (WQFN-16); Alternate PartNumber: ADS122U04IRTET; Alternate Manufacturer: Texas Instruments; SizeAreaWB_mm2: 16; SizeZ_mm: 0.8; SizeX_mm: 3; SizeArea_mm2: 9; CompType: IC; AEC Category: Q200; AEC Qualified: N; Rating: Catalog
U5 = CMP-0081843-1: High Speed, Robust EMC Reinforced Dual-Channel Digital Isolator, DWV0008A (SOIC-8); Alternate PartNumber: ISO7721DWVR; Alternate Manufacturer: Texas Instruments; SizeAreaWB_mm2: 105.975; Rating: Catalog; SizeZ_mm: 2.8; SizeX_mm: 11.5; SizeY_mm: 5.85; SizeArea_mm2: 67.275; CompType: IC; AEC Qualified: N; AEC Category: Q200

## Sheet TIDA-010048_CoverSheet.SchDoc
size 431 x 279 mm; Date: Not shown in title block; ApprovedBy: Not shown in title block; CheckedBy: Not shown in title block; Author: Not shown in title block; CompanyName: Not shown in title block; Engineer: Not shown in title block; Organization: Not shown in title block; Address1: Not shown in title block; Address2: Not shown in title block; Address3: Not shown in title block; Address4: Not shown in title block; DocumentNumber: 1; Revision: Use project parameter SCH_Rev; SheetNumber: 1; SheetTotal: 3; PageSetup: Record=PageOptions¦CenterHorizontal=True¦CenterVertical=True¦PrintScale=1.00¦XCorrection=1.00¦YCorrection=1.00¦PrintKind=0¦BorderSize=5000000¦LeftOffset=0¦BottomOffset=0¦Orientation=2¦PaperLength=1000¦PaperWidth=1000¦Scale=100¦PaperSource=15¦PrintQuality=600¦MediaType=1¦DitherType=10¦PaperKind=Letter¦PrintScaleMode=1
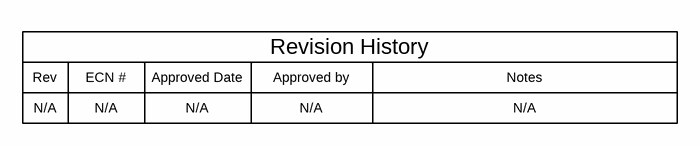
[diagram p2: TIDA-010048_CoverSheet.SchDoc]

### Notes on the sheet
- Rev
- N/A
- ECN #
- Approved Date
- Approved by
- Revision History
- Notes

## Sheet TIDA-010048_EVM_Hardware.SchDoc
size 431 x 279 mm; Date: Not shown in title block; ApprovedBy: Not shown in title block; CheckedBy: Not shown in title block; Author: Not shown in title block; CompanyName: Not shown in title block; Engineer: Not shown in title block; Organization: Not shown in title block; Address1: Not shown in title block; Address2: Not shown in title block; Address3: Not shown in title block; Address4: Not shown in title block; DocumentNumber: 1; Revision: Use project parameter SCH_Rev; SheetNumber: 3; SheetTotal: 3; PageSetup: Record=PageOptions¦CenterHorizontal=True¦CenterVertical=True¦PrintScale=1.00¦XCorrection=1.00¦YCorrection=1.00¦PrintKind=0¦BorderSize=5000000¦LeftOffset=0¦BottomOffset=0¦Orientation=2¦PaperLength=1000¦PaperWidth=1000¦Scale=100¦PaperSource=15¦PrintQuality=600¦MediaType=1¦DitherType=10¦PaperKind=Letter¦PrintScaleMode=1
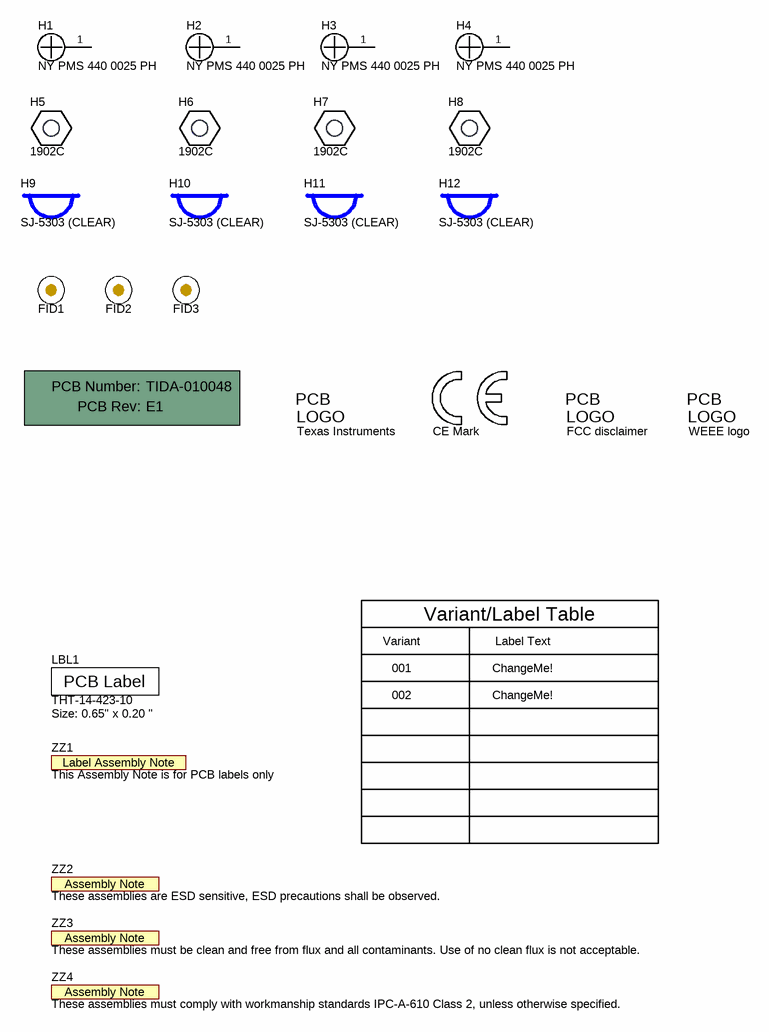
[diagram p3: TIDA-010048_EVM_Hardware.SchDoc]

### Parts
!PCB1  Printed Circuit Board  (value not drawn)  (mechanical)
FID1  Fiducial  [Fiducial10-20]  (value not drawn)
FID2  Fiducial  [Fiducial10-20]  (value not drawn)
FID3  Fiducial  [Fiducial10-20]  (value not drawn)
H1  NY PMS 440 0025 PH  [NY PMS 440 0025 PH]
H2  NY PMS 440 0025 PH  [NY PMS 440 0025 PH]
H3  NY PMS 440 0025 PH  [NY PMS 440 0025 PH]
H4  NY PMS 440 0025 PH  [NY PMS 440 0025 PH]
H5  1902C  [Keystone_1902C]
H6  1902C  [Keystone_1902C]
H7  1902C  [Keystone_1902C]
H8  1902C  [Keystone_1902C]
H9  SJ-5303 (CLEAR)  [Bumpon_SJ5003Transparent]
H10  SJ-5303 (CLEAR)  [Bumpon_SJ5003Transparent]
H11  SJ-5303 (CLEAR)  [Bumpon_SJ5003Transparent]
H12  SJ-5303 (CLEAR)  [Bumpon_SJ5003Transparent]
LBL1  THT-14-423-10  Note: Size: 0.65" x 0.20 "  [Label_650x200]
Logo1  CE Mark  [CE_Mark_5mm]  (no BOM)
Logo2  Texas Instruments  [TI_Stacked_Overlay_Small]  (no BOM)
Logo3  FCC disclaimer  [FCC_disclaimer]  (no BOM)
Logo4  WEEE logo  [WEEE_Minimum]  (no BOM)
ZZ1  This Assembly Note is for PCB labels only  [AssemblyNoteLabel]  (no BOM)
ZZ2  These assemblies are ESD sensitive, ESD precautions shall be observed.  [AssemblyNote]  (no BOM)
ZZ3  These assemblies must be clean and free from flux and all contaminants. Use of no clean flux is not acceptable.  [AssemblyNote]  (no BOM)
ZZ4  These assemblies must comply with workmanship standards IPC-A-610 Class 2, unless otherwise specified.  [AssemblyNote]  (no BOM)

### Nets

Not connected (* = marked no-connect by the designer): H1 1; H2 1; H3 1; H4 1

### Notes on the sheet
- Variant
- Variant/Label Table
- Label Text
- 001
- 002
- ChangeMe!

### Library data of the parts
!PCB1 = CMP-0003618-2: Manufacturer: Any; PartNumber: TIDA-010048
FID1-FID3 = CMP-0077181-1: Fiducial mark.  There is nothing to buy or mount.
H1-H4 = CMP-0003617-1: Machine Screw, Round, #4-40 x 1/4, Nylon, Philips panhead; Manufacturer: B&F Fastener Supply; CompType: Hardware
H5-H8 = CMP-0003610-1: Standoff, Hex, 0.5"L #4-40 Nylon; Manufacturer: Keystone; CompType: Hardware
H9-H12 = CMP-0003620-1: Bumpon, Hemisphere, 0.44 X 0.20, Clear; Manufacturer: 3M
LBL1 = CMP-0003625-1: Thermal Transfer Printable Labels, 0.650" W x 0.200" H - 10,000 per roll; Manufacturer: Brady; CompType: Label
Logo1 = CMP-0074844-1: SymbolCreator: a0412235
Logo2 = CMP-0074838-1: Texas Instrument Corporate Signature; SymbolCreator: a0412235; Lib Reference: TI_Logo; Library Reference: Logo
Logo3 = CMP-0074847-1: FCC_disclaimer; Library Reference: Logo
Logo4 = CMP-0074769-1
ZZ1 = CMP-0003616-3
ZZ2 = CMP-0077236-1
ZZ3 = CMP-0077237-1
ZZ4 = CMP-0077238-1

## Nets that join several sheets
BGND: TIDA-010048_topLevel (18 pins), CH1 (C10_CH1.2 U5_CH1.5), CH2 (C10_CH2.2 U5_CH2.5), CH3 (C10_CH3.2 U5_CH3.5), CH4 (C10_CH4.2 U5_CH4.5)
BVCC: TIDA-010048_topLevel (5 pins), CH1 (C10_CH1.1 U5_CH1.8), CH2 (C10_CH2.1 U5_CH2.8), CH3 (C10_CH3.1 U5_CH3.8), CH4 (C10_CH4.1 U5_CH4.8)
GND: TIDA-010048_topLevel (8 pins), CH1 (27 pins), CH2 (27 pins), CH3 (27 pins), CH4 (27 pins)
ADC_RX1: TIDA-010048_topLevel (R19.2), CH1 (U5_CH1.7)
ADC_RX2: TIDA-010048_topLevel (R20.2), CH2 (U5_CH2.7)
ADC_RX3: TIDA-010048_topLevel (R21.2), CH3 (U5_CH3.7)
ADC_RX4: TIDA-010048_topLevel (R22.2), CH4 (U5_CH4.7)
ADC_TX1: TIDA-010048_topLevel (R23.2), CH1 (U5_CH1.6)
ADC_TX2: TIDA-010048_topLevel (R24.2), CH2 (U5_CH2.6)
ADC_TX3: TIDA-010048_topLevel (R25.2), CH3 (U5_CH3.6)
ADC_TX4: TIDA-010048_topLevel (R26.2), CH4 (U5_CH4.6)
iso_power1: TIDA-010048_topLevel (T1.2), CH1 (D1_CH1.2)
iso_power2: TIDA-010048_topLevel (T1.4), CH2 (D1_CH2.2)
iso_power3: TIDA-010048_topLevel (T1.6), CH3 (D1_CH3.2)
iso_power4: TIDA-010048_topLevel (T1.8), CH4 (D1_CH4.2)

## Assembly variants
001: not fitted FID1 FID2 FID3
